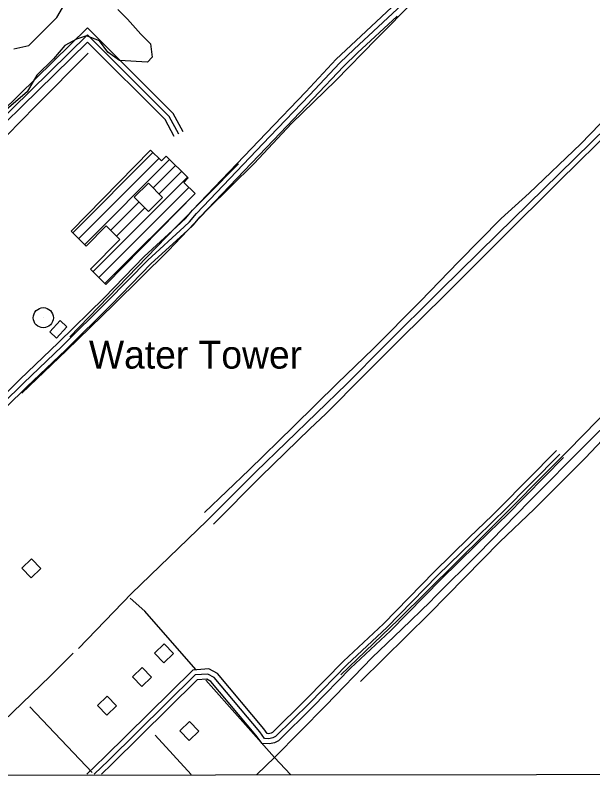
# Model space of a CAD drawing. Extents: x 3297772 to 3335630, y 634068 to 659439.
# Drawn here: x 3308939 to 3310660, y 639447 to 641721 of the extents above; entities that cross this region are included whole.
import ezdxf

# ---------------------------------------------------------------- set-up
doc = ezdxf.new("R2010")
doc.units = 0
for name, color, linetype in [('V-BLDG-OTLN', 7, 'Continuous'), ('V-DOMW-IDEN', 7, 'Continuous'), ('V-DOMW-TANK', 7, 'Continuous'), ('V-DTCH-CNTR', 7, 'Continuous'), ('V-GRID-FRAM', 7, 'Continuous'), ('V-ROAD-CNTR', 7, 'Continuous'), ('V-SITE-VEGE', 7, 'Continuous'), ('V-TOPO-SHOR', 7, 'Continuous')]:
    doc.layers.add(name, color=color, linetype=linetype)

msp = doc.modelspace()

# ---------------------------------------------------------------- linework, layer by layer
at = {"layer": 'V-BLDG-OTLN'}
for p, q in [((3309109.9, 641072.1), (3309349, 641311.2)), ((3309127.8, 641054.7), (3309366.9, 641293.8)), ((3309145.7, 641037.2), (3309398.6, 641290.1)), ((3309348.8, 641205), (3309416.5, 641272.6)), ((3309367.5, 641188.3), (3309434.3, 641255.1)), ((3309170.3, 640955.8), (3309452.2, 641237.6)), ((3309188.2, 640938.3), (3309456.6, 641206.7)), ((3309206.1, 640920.8), (3309474.5, 641189.2)), ((3309222.8, 641079), (3309308.2, 641164.3)), ((3309240.7, 641061.5), (3309325.4, 641146.2))]:
    msp.add_line(p, q, dxfattribs=at)
for points in [[(3309474.5, 641189.2), (3309209, 640918), (3309162.9, 640963.1), (3309250.1, 641052.3), (3309209.2, 641092.3), (3309150.5, 641032.4), (3309105.6, 641076.4), (3309342.1, 641318), (3309374.8, 641286), (3309388.5, 641300), (3309454.3, 641235.6), (3309441, 641222)], [(3309335.5, 641135.4), (3309293.2, 641178.6), (3309335.9, 641220.3), (3309378.1, 641177.1)], [(3309061.7, 640758), (3309092.5, 640791.6), (3309072.4, 640810.1), (3309041.6, 640776.5)], [(3308985.9, 640042.8), (3309014.9, 640070.3), (3308987.5, 640099.3), (3308958.4, 640071.9)], [(3309381.1, 639789.6), (3309409.9, 639817.4), (3309382.1, 639846.1), (3309353.3, 639818.3)], [(3309316, 639718.7), (3309344.8, 639746.5), (3309317, 639775.3), (3309288.3, 639747.5)], [(3309211.9, 639633), (3309240.7, 639660.8), (3309212.9, 639689.6), (3309184.1, 639661.8)], [(3309458.5, 639614.3), (3309429.5, 639586.7), (3309457, 639557.7), (3309486, 639585.2)]]:
    msp.add_lwpolyline(points, close=True, dxfattribs=at)
at = {"layer": 'V-DOMW-TANK'}
msp.add_line((3309022.3, 640818.6), (3309022.3, 640818.6), dxfattribs=at)
msp.add_circle((3309022.3, 640818.6), 30, dxfattribs=at)
at = {"layer": 'V-DTCH-CNTR'}
for points in [[(3308957.8, 640593.1), (3309091.9, 640721.3), (3309232.2, 640858.2), (3309394.3, 641017.7), (3309511.7, 641141.7), (3309650.7, 641278.7), (3309762.4, 641397.7), (3309894.7, 641525.6), (3310014.9, 641649.2), (3310130, 641766.6), (3310258, 641899.9), (3310432.2, 642070.3), (3310569.9, 642206.9), (3310731.1, 642369.6), (3310872.3, 642504), (3311008.6, 642622.7), (3311079.8, 642684.7), (3311279.3, 642883.5)], [(3310803.1, 641453.6), (3310801.3, 641454.4), (3310793.7, 641457.8), (3310791, 641457.8), (3310771, 641483.7), (3310768.4, 641485.1), (3310765.6, 641483.8), (3310624.8, 641337), (3310470.5, 641190.3), (3310387.2, 641114.3), (3310260.1, 640984.9), (3310146.7, 640867.5), (3310005.9, 640726.1), (3309899.4, 640623.4), (3309768.2, 640494), (3309635.7, 640364.6), (3309503.2, 640238)], [(3309529.8, 640202.5), (3309670.6, 640345.3), (3309816.7, 640486.7), (3309864.5, 640532), (3309978, 640646.7), (3310085.9, 640754.8), (3310219.8, 640886.8), (3310385.1, 641052.3), (3310560, 641225.7), (3310728.1, 641391.1), (3310801.3, 641454.4)], [(3311176.6, 640983), (3311078.3, 640891), (3310717.9, 640556.4), (3310586.7, 640423), (3310340.7, 640174.9), (3310079.8, 639917.4), (3309909, 639753.4)], [(3309968.2, 639733.8), (3310173.1, 639936.6), (3310383.6, 640150), (3310486, 640247.4), (3310637.7, 640399.4), (3310756.7, 640526.3), (3310846.8, 640608.9), (3310932.8, 640690.2), (3311020.1, 640764.8), (3311103.5, 640848.8), (3311170.4, 640914.2), (3311206.3, 640947.9)]]:
    msp.add_lwpolyline(points, dxfattribs=at)
at = {"layer": 'V-GRID-FRAM'}
msp.add_lwpolyline([(3301870.2, 657630.6), (3333425.5, 657662.7), (3333452, 639478.7), (3301880.8, 639446.5), (3301870.2, 657630.6)], dxfattribs=at)
at = {"layer": 'V-ROAD-CNTR'}
for points in [[(3308230.5, 639929.4), (3308253.4, 639940.6), (3308273.1, 639954.7), (3308298.4, 639973.2), (3308335.9, 640016.1), (3308378.2, 640059.3), (3308480.3, 640146.8), (3308579, 640243.8), (3308699.6, 640358.9), (3308838.3, 640501.4), (3308962.9, 640623.2), (3309078.5, 640734), (3309213.9, 640867.6), (3309333.6, 640990.5), (3309442.1, 641090), (3309458.2, 641104.8), (3309478.5, 641129.4), (3309697.8, 641358.7), (3309816.1, 641482.4), (3309906.1, 641578.7), (3309948.9, 641619.7), (3310092, 641753)], [(3308237.5, 639949.5), (3308245.7, 639953.5), (3308264.3, 639966.9), (3308288.2, 639984.4), (3308324.9, 640026.3), (3308368, 640070.3), (3308470.2, 640157.9), (3308568.6, 640254.5), (3308689, 640369.5), (3308827.7, 640512), (3308952.4, 640634), (3309068, 640744.7), (3309203.3, 640878.2), (3309323.2, 641001.3), (3309432, 641101.1), (3309447.3, 641115.2), (3309467.3, 641139.4), (3309687, 641369.1), (3309805.2, 641492.7), (3309895.4, 641589.3), (3309938.6, 641630.6), (3310076.2, 641758.7)], [(3308250.4, 639922.4), (3308261.2, 639927.6), (3308281.9, 639942.6), (3308308.6, 639962.1), (3308346.9, 640005.9), (3308388.5, 640048.3), (3308490.5, 640135.8), (3308589.5, 640233), (3308710.1, 640348.2), (3308848.9, 640490.8), (3308973.3, 640612.5), (3309089, 640723.2), (3309224.6, 640857), (3309344.1, 640979.8), (3309452.3, 641079), (3309469.1, 641094.5), (3309489.8, 641119.5), (3309708.6, 641348.4), (3309827, 641472.1), (3309916.7, 641568.2), (3309959.2, 641608.8), (3310076.8, 641718.3)], [(3309439.2, 641373.1), (3309409.8, 641427.6), (3309154.5, 641682.9), (3308692, 641230.7), (3308443, 640985.7), (3308353, 640831.2), (3308338.7, 640810), (3308334.7, 640805.7)], [(3309426, 641365.9), (3309397.6, 641418.5), (3309154.4, 641661.8), (3308702.5, 641220), (3308455, 640976.5), (3308365.7, 640823.3), (3308350.5, 640800.6), (3308269.5, 640714.7), (3307933.5, 640392.8)], [(3309412.8, 641358.8), (3309385.5, 641409.5), (3309154.3, 641640.7), (3308713, 641209.3), (3308466.9, 640967.2), (3308378.4, 640815.3), (3308362.3, 640791.2), (3308354, 640782.5)], [(3310551.7, 640422.4), (3310381.8, 640250.1), (3310361.1, 640230.1), (3310291.9, 640162.9), (3310187.3, 640060.3), (3310036.4, 639905.7), (3309917.3, 639794.7), (3309804.8, 639679.7), (3309705.3, 639581.7), (3309701.2, 639579.6), (3309693.5, 639578), (3309689.9, 639578.1), (3309679.7, 639592.4), (3309541.1, 639757.9), (3309516, 639770.9), (3309468, 639767.7)], [(3310562.3, 640411.9), (3310392.4, 640239.5), (3310371.5, 640219.3), (3310302.4, 640152.1), (3310197.9, 640049.7), (3310046.8, 639895), (3309927.8, 639783.9), (3309815.4, 639669.1), (3309714.2, 639569.4), (3309706.2, 639565.3), (3309694.8, 639563), (3309682.1, 639563.2), (3309667.8, 639583.2), (3309531.5, 639746), (3309512.8, 639755.7), (3309474.6, 639753.1)], [(3310573, 640401.4), (3310402.9, 640228.8), (3310382, 640208.5), (3310312.9, 640141.4), (3310208.6, 640039.1), (3310057.3, 639884.3), (3309938.3, 639773.2), (3309826, 639658.5), (3309723.1, 639557.1), (3309711.3, 639551), (3309696.2, 639548), (3309674.3, 639548.4), (3309656, 639574), (3309521.9, 639734), (3309509.6, 639740.4), (3309481.1, 639738.5)], [(3309152.4, 639457.4), (3309205.8, 639508.5), (3309468, 639767.7)], [(3309173.6, 639457), (3309216.3, 639497.8), (3309474.6, 639753.1)], [(3309195.4, 639457), (3309226.7, 639487), (3309481.1, 639738.5)]]:
    msp.add_lwpolyline(points, dxfattribs=at)
at = {"layer": 'V-SITE-VEGE'}
for points in [[(3308934.6, 641620.3), (3308978.8, 641630.1), (3309062.3, 641713.7), (3309096.7, 641772.7)], [(3309244.1, 641738.2), (3309273.5, 641708.8), (3309312.8, 641664.5), (3309342.3, 641635), (3309347.2, 641595.7), (3309332.5, 641580.9), (3309249, 641585.9), (3309214.6, 641610.4), (3309190, 641644.8), (3309150.7, 641659.6), (3309121.3, 641649.8), (3309086.9, 641630.1), (3309052.5, 641590.8), (3309003.4, 641541.6), (3308973.9, 641492.5), (3308836.3, 641374.5)]]:
    msp.add_lwpolyline(points, dxfattribs=at)
at = {"layer": 'V-TOPO-SHOR'}
for p, q in [((3308982.4, 639657.7), (3309168.1, 639462.1)), ((3309355.9, 639573.6), (3309463.4, 639456.3)), ((3309711.8, 639507.1), (3309758.7, 639456.3))]:
    msp.add_line(p, q, dxfattribs=at)
for points in [[(3308751.4, 641188.2), (3308763.8, 641216.2), (3308776.2, 641233.3), (3308913.1, 641362.3), (3308998.6, 641449.4), (3309155.6, 641608)], [(3309510.2, 640213.2), (3309656.1, 640358.8), (3309926.7, 640621.8), (3310039.5, 640734.3), (3310207.6, 640901.6), (3310376.5, 641067.7), (3310559.9, 641247.9), (3310703.6, 641387.9), (3310774.7, 641460.3)], [(3309101, 640762), (3309417.3, 641088.4), (3309604.2, 641277.4)], [(3311179, 640954.3), (3311130.3, 640903.9), (3310939, 640730.3), (3310799.2, 640598.1), (3310643.6, 640444.4), (3310471.6, 640271.5), (3310318.8, 640114.5), (3310190.8, 639987), (3310175.4, 639971), (3310091.2, 639890.1), (3310002.9, 639805.4)], [(3309510.2, 640213.2), (3309285.5, 639996), (3309127.1, 639831.7)], [(3309477.1, 639769.2), (3309324.6, 639943.2), (3309281.6, 639982.3)], [(3309111.4, 639818), (3309043, 639749.6), (3308736, 639454.3)], [(3309711.8, 639507.1), (3309864.3, 639661.6), (3310002.9, 639805.4)], [(3309506.4, 639737.9), (3309711.8, 639507.1), (3309659, 639456.3)]]:
    msp.add_lwpolyline(points, dxfattribs=at)

# ---------------------------------------------------------------- texts
at = {"layer": 'V-DOMW-IDEN'}
msp.add_text('Water Tower', height=83, dxfattribs=at).set_placement((3309158.4, 640666.8))

doc.saveas('drawing.dxf')
